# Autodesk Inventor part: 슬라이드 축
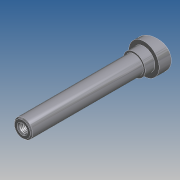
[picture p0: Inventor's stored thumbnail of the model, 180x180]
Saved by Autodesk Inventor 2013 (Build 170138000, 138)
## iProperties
Company: 한국ATC센터
Created: 2014-07
Part Number: 슬라이드 축
Document SubType Name: 모델링
Designer: KYOUNG IL JANG
Mass: 21.572 g
Surface Area: 67.5858 cm^2
Volume: 21.572 cm^3
Density: 1 g/cm^3
Material: 일반
변환 표준: STEP AP214IS
파일 이름: C:\Users\SeoGD\Desktop\?쒗뿕\異?stp
전처리기: Build: 253, Release: 2010 SP1 - Date: Wed 07/29/2009
전송 단위: 밀리미터
불확실성: 0.01
Author: KYOUNG IL JANG
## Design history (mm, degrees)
sketch "스케치1"
  geometry: L1 (0, 100)-(7.5, 100); L2 (7.5, 100)-(7.5, 0); L3 (7.5, 0)-(12.5, 0); L4 (12.5, 0)-(12.5, -17); L5 (12.5, -17)-(0, -17); L6 (0, -17)-(0, 100); 1 further point
  constraints: 12 end point, 2 parallel, 2 point on line, 1 perpendicular, 1 vertical
  dimensions: "d0" = 100 distance from line of L1 point (0, 0); "d1" = 15 diameter of L2 L6; "d2" = 25 diameter of L4 L6; "d3" = 17 distance of L3.end L4.end
revolve "회전1" sketch "스케치1" stored, may be unused: angle "d4" = 90 deg
sketch "스케치2"
  geometry: L1 (12.5, 0)-(12.5, -17) reference; L2 (-12.5, -17)-(12.5, -17) reference; L3 (-12.5, 0)-(-12.5, -17) reference; L4 (12.5, -5)-(-12.5, -11.699); L5 (-12.5, 0)-(12.5, 0) reference; 1 further point
  constraints: 2 end point, 2 point on line
  dimensions: "d5" = 75 deg angle of L1 L4; "d6" = 5 distance from line of L4.start L5
extrude "돌출1" cut sketch "스케치2" stored distance "d7" = 10; taper "d8" = 0 deg
chamfer "모따기1" distance "d9" = 1; stored, may be unused: second distance "d10" = 2, angle "d11" = 45 deg
fillet "모깎기1" dims "d12" = 0.5
hole "구멍1" diameter "d15" = 6.647; stored, may be unused: countersink angle "d19" = 90 deg, drill point angle "d21" = 118 deg; dims "d13" = 10, "d14" = 10, "d16" = 17, "d17" = 4, "d18" = 2, "d20" = 20
chamfer "모따기2" distance "d22" = 1; stored, may be unused: second distance "d23" = 2, angle "d24" = 45 deg
sketch "스케치3"
  geometry: C1 r 9 at (0, 0); 1 further point
  constraints: 1 centre point, 1 coincident
  dimensions: "d25" = 18 diameter of C1
extrude "돌출2" join sketch "스케치3" distance "d26" = 8; taper "d27" = 0 deg
node "솔리드1"
node "솔리드 본체"
node "곡면 본체"
node "솔리드2"
